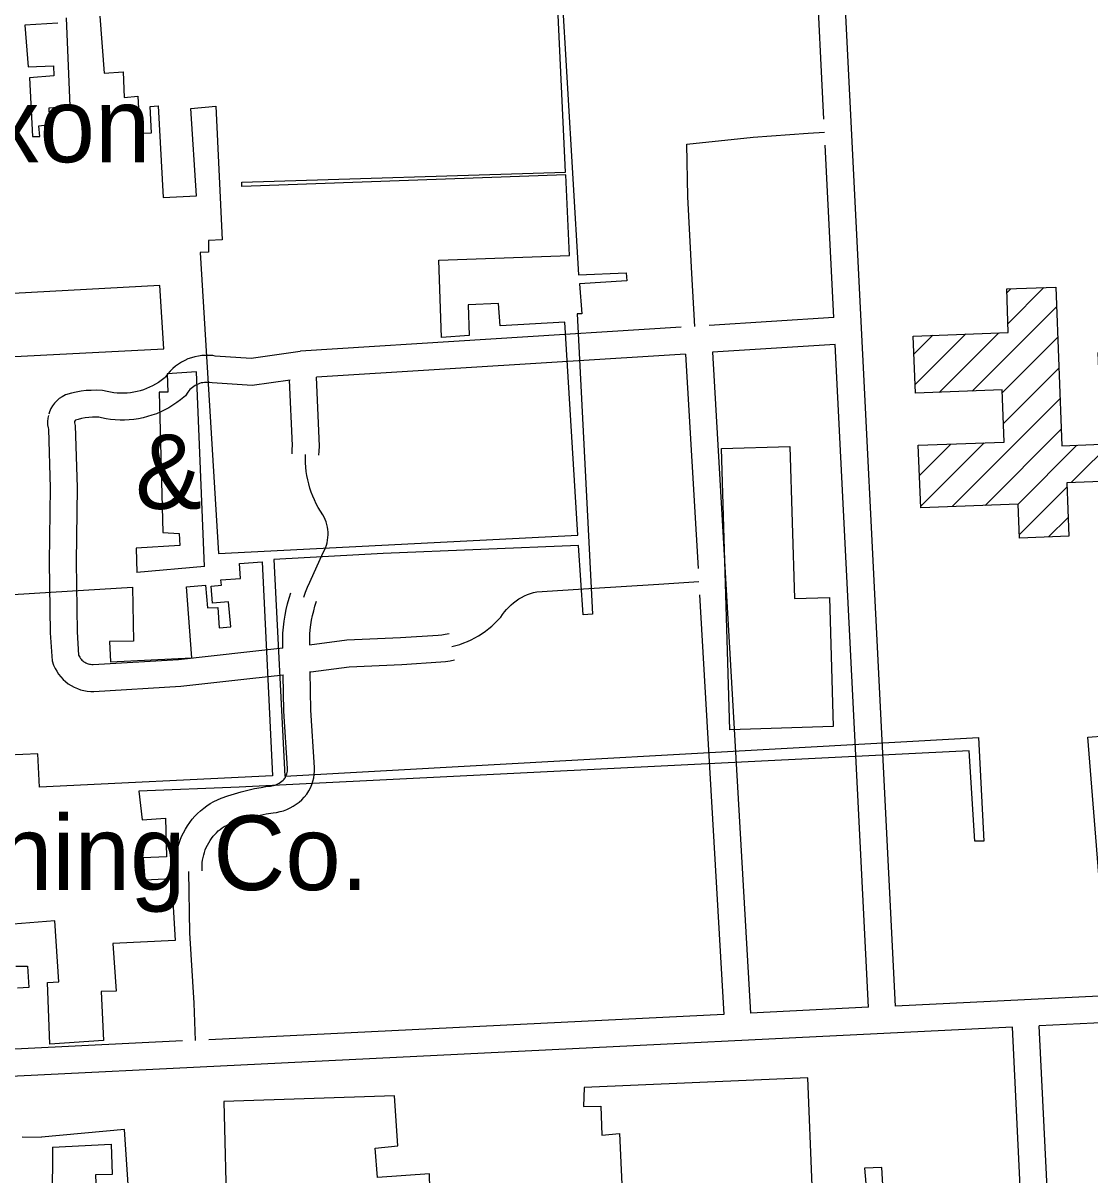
# Model space of a CAD drawing. Extents: x 3313447 to 3351316, y 703786 to 729172.
# Drawn here: x 3330659 to 3331846, y 721489 to 722771 of the extents above; entities that cross this region are included whole.
import ezdxf

# ---------------------------------------------------------------- set-up
doc = ezdxf.new("R2010")
doc.units = 0
for name, color, linetype in [('V-BLDG-IDEN', 7, 'Continuous'), ('V-BLDG-OTLN', 7, 'Continuous'), ('V-ROAD-CNTR', 7, 'Continuous'), ('V-UTIL-LINE', 7, 'Continuous')]:
    doc.layers.add(name, color=color, linetype=linetype)

msp = doc.modelspace()

# ---------------------------------------------------------------- linework, layer by layer
at = {"layer": 'V-BLDG-OTLN'}
for p, q in [((3331753.5, 722470.9), (3331758, 722475.5)), ((3331754.8, 722436.9), (3331794.8, 722476.9)), ((3331714.9, 722361.6), (3331808.6, 722455.4)), ((3331650.1, 722402.9), (3331671, 722423.8)), ((3331651.4, 722368.9), (3331707.8, 722425.2)), ((3331678.1, 722360.2), (3331744.5, 722426.6)), ((3331748.3, 722359.7), (3331809.9, 722421.3)), ((3331825.2, 722259.8), (3331968.9, 722403.5)), ((3331749.6, 722325.7), (3331811.3, 722387.3)), ((3331692.5, 722233.1), (3331812.6, 722353.2)), ((3331729.2, 722234.5), (3331813.9, 722319.2)), ((3331657.6, 722233.6), (3331728.1, 722304.1)), ((3331656.2, 722267.6), (3331691.3, 722302.7)), ((3331766, 722236), (3331831.5, 722301.5)), ((3331767.5, 722202.1), (3331820.5, 722255.1)), ((3331800, 722199.3), (3331821.8, 722221))]:
    msp.add_line(p, q, dxfattribs=at)
for points in [[(3331974.2, 722265.5), (3331820.3, 722259.6), (3331822.6, 722200.1), (3331767.6, 722198), (3331766.2, 722236), (3331657.6, 722231.8), (3331654.9, 722301.3), (3331750.4, 722305), (3331748.2, 722362.9), (3331651.8, 722359.2), (3331649.4, 722422.9), (3331755.1, 722427), (3331753.3, 722475.3), (3331807.8, 722477.4), (3331814.6, 722300.8), (3331859, 722302.6), (3331855, 722404.5), (3331968.7, 722408.9)], [(3331435.9, 722297.7), (3331512, 722300), (3331517.1, 722130.8), (3331556.1, 722131.9), (3331560.4, 721988.2), (3331445.2, 721984.7)], [(3331863.1, 721730.7), (3331843.7, 721976.4), (3331863.4, 721977.9), (3331856.9, 722060.5), (3331928, 722066.1), (3331933.8, 721992.1), (3331962.2, 721994.4), (3331982.3, 721740.1)]]:
    msp.add_lwpolyline(points, close=True, dxfattribs=at)
at = {"layer": 'V-ROAD-CNTR'}
for points in [[(3331550, 722664.2), (3331541.2, 722838.3)], [(3331629.7, 721677.3), (3331571.2, 722839.5)], [(3331406.4, 722433.7), (3331403.1, 722492.7), (3331398.4, 722578), (3331397.5, 722636.6), (3331471.1, 722644.2), (3331532.4, 722648.7), (3331550.7, 722650)], [(3331561.1, 722443.4), (3331551.4, 722635.2)], [(3331391.2, 722432.7), (3330967.7, 722406)], [(3331561.1, 722443.4), (3331422.4, 722434.7)], [(3330967.3, 722405.6), (3330912.6, 722398), (3330872.7, 722400.6), (3330869.9, 722401.1), (3330865.9, 722401.4), (3330861.9, 722401.4), (3330857.9, 722401.2), (3330853.9, 722400.6), (3330850, 722399.8), (3330846.1, 722398.7), (3330842.3, 722397.4), (3330838.7, 722395.7), (3330835.1, 722393.8), (3330831.7, 722391.7), (3330828.5, 722389.3), (3330825.4, 722386.7), (3330822.6, 722383.9), (3330819.9, 722380.9), (3330817.5, 722377.7), (3330816.9, 722376.6), (3330815.5, 722375.5), (3330812.5, 722373.3), (3330809.4, 722371.2), (3330806.3, 722369.3), (3330803, 722367.5), (3330799.7, 722365.9), (3330796.3, 722364.5), (3330792.8, 722363.2), (3330789.2, 722362.1), (3330785.7, 722361.2), (3330782, 722360.5), (3330778.4, 722359.9), (3330774.7, 722359.5), (3330771, 722359.4), (3330767.3, 722359.3), (3330763.6, 722359.5), (3330759.9, 722359.9), (3330756.2, 722360.4), (3330752.6, 722361.1), (3330747.1, 722362.5), (3330740.3, 722362.7), (3330734.7, 722362.5), (3330729.2, 722362.2), (3330723.6, 722361.5), (3330718.1, 722360.5), (3330712.7, 722359.3), (3330706.1, 722357.4), (3330702.2, 722355.4), (3330699.1, 722353.3), (3330696.3, 722350.9), (3330693.8, 722348.2), (3330691.6, 722345.2), (3330689.8, 722342.1), (3330688.3, 722338.7), (3330687.4, 722336)], [(3331562.6, 722413.4), (3331426.1, 722404.8)], [(3331599.7, 721675.9), (3331562.6, 722413.4)], [(3331396.1, 722402.9), (3330985.2, 722377)], [(3331396.1, 722402.9), (3331409.9, 722164.4)], [(3331426.1, 722404.8), (3331468.4, 721669.4)], [(3330956.2, 722373.8), (3330913.7, 722367.8), (3330869.4, 722370.8), (3330866.4, 722371.2), (3330864.5, 722371.4), (3330862.7, 722371.4), (3330860.8, 722371.3), (3330858.9, 722371), (3330857.1, 722370.7), (3330855.3, 722370.2), (3330853.6, 722369.5), (3330851.9, 722368.8), (3330850.2, 722367.9), (3330848.7, 722366.9), (3330847.2, 722365.8), (3330845.7, 722364.6), (3330844.4, 722363.3), (3330843.2, 722361.9), (3330842.1, 722360.4), (3330839.5, 722356.5), (3330834.1, 722351.9), (3330829.9, 722348.8), (3330825.6, 722345.9), (3330821.2, 722343.2), (3330816.6, 722340.8), (3330812, 722338.5), (3330807.2, 722336.5), (3330802.3, 722334.8), (3330797.4, 722333.3), (3330792.4, 722332), (3330787.3, 722330.9), (3330782.2, 722330.2), (3330777, 722329.6), (3330771.8, 722329.4), (3330766.7, 722329.3), (3330761.5, 722329.6), (3330756.3, 722330.1), (3330751.2, 722330.8), (3330746.1, 722331.8), (3330743, 722332.6), (3330740.2, 722332.7), (3330736.1, 722332.6), (3330732, 722332.3), (3330728, 722331.8), (3330724, 722331.1), (3330720.1, 722330.2), (3330717.3, 722329.4), (3330717.7, 722329.6), (3330717.4, 722329.4), (3330717.1, 722329.2), (3330716.9, 722328.9), (3330716.7, 722328.6), (3330716.5, 722328.3), (3330716.3, 722328), (3330716, 722326.9)], [(3330958.1, 722292), (3330958.4, 722297.1), (3330958.8, 722301), (3330955.4, 722373.7)], [(3330988, 722290.2), (3330988.3, 722294.7), (3330988.8, 722300.2), (3330985.3, 722377)], [(3330687, 722334.4), (3330686.4, 722331.6), (3330686.1, 722327.9), (3330686.2, 722324.2), (3330686.7, 722320.6), (3330687, 722319.4), (3330689.1, 722254), (3330688, 722171.5), (3330689, 722092.5), (3330691.1, 722061.5), (3330692.8, 722056.6), (3330694.4, 722053.1), (3330696.3, 722049.8), (3330698.4, 722046.6), (3330700.7, 722043.6), (3330703.3, 722040.8), (3330706.2, 722038.3), (3330709.2, 722035.9), (3330712.4, 722033.9), (3330715.8, 722032.1), (3330719.3, 722030.6), (3330722.9, 722029.3), (3330726.6, 722028.4), (3330730.3, 722027.8), (3330734.1, 722027.5), (3330737.7, 722027.5), (3330834.4, 722033.2), (3330911, 722041.7), (3330948.6, 722045.7)], [(3330716.4, 722328.5), (3330716.2, 722327.3), (3330716.1, 722327), (3330716.1, 722326.6), (3330716.2, 722326.2), (3330716.9, 722323.5), (3330719.1, 722254.3), (3330718, 722171.5), (3330719, 722093.7), (3330720.7, 722067.7), (3330720.7, 722067.8), (3330721.3, 722066.5), (3330721.9, 722065.4), (3330722.7, 722064.2), (3330723.5, 722063.2), (3330724.4, 722062.2), (3330725.4, 722061.3), (3330726.5, 722060.5), (3330727.6, 722059.8), (3330728.8, 722059.1), (3330730, 722058.6), (3330731.3, 722058.2), (3330732.6, 722057.8), (3330733.9, 722057.6), (3330735.3, 722057.5), (3330736.8, 722057.5), (3330831.8, 722063.1), (3330907.7, 722071.5), (3330948, 722075.8)], [(3330971.1, 722132.4), (3330973.2, 722138), (3330975.5, 722143.5), (3330978, 722148.9), (3330992.8, 722182), (3330994.2, 722184.6), (3330995.4, 722187.3), (3330996.4, 722190.1), (3330997.1, 722192.9), (3330997.7, 722195.8), (3330998.1, 722198.7), (3330998.3, 722201.6), (3330998.2, 722204.6), (3330998, 722207.5), (3330997.5, 722210.4), (3330996.9, 722213.3), (3330996, 722216.1), (3330995, 722218.8), (3330993.8, 722221.5), (3330992.3, 722224.1), (3330989.7, 722228), (3330987.3, 722232.1), (3330985.1, 722236.3), (3330983, 722240.5), (3330981.2, 722244.9), (3330979.5, 722249.3), (3330978, 722253.8), (3330976.7, 722258.3), (3330975.6, 722262.9), (3330974.6, 722267.6), (3330973.9, 722272.3), (3330973.4, 722277), (3330973.1, 722281.7), (3330973, 722286.4), (3330973, 722291.1)], [(3331135.9, 722077.3), (3331140.3, 722078.5), (3331144.7, 722079.8), (3331149.1, 722081.4), (3331153.3, 722083.1), (3331157.5, 722085), (3331161.6, 722087.1), (3331165.6, 722089.4), (3331169.5, 722091.9), (3331173.3, 722094.5), (3331177, 722097.3), (3331180.5, 722100.2), (3331183.9, 722103.3), (3331187.1, 722106.6), (3331190.3, 722110), (3331192.2, 722113), (3331194.4, 722115.9), (3331196.7, 722118.7), (3331199.2, 722121.3), (3331201.8, 722123.8), (3331204.6, 722126.1), (3331207.5, 722128.3), (3331210.5, 722130.3), (3331213.6, 722132.1), (3331216.8, 722133.7), (3331220.1, 722135.2), (3331223.5, 722136.5), (3331226.9, 722137.5), (3331230.4, 722138.4), (3331288.3, 722142), (3331366.4, 722146.6), (3331410.7, 722149.6)], [(3330948, 722075.7), (3330947.9, 722092.2), (3330948.5, 722099.1), (3330949.3, 722105.6), (3330950.3, 722112.1), (3330951.6, 722118.5), (3330953.2, 722124.8), (3330954.9, 722131.1), (3330956.9, 722137.1)], [(3330978, 722079.1), (3330977.9, 722091.1), (3330978.3, 722096.1), (3330979, 722101.4), (3330979.8, 722106.7), (3330980.9, 722112), (3330982.2, 722117.2), (3330983.6, 722122.4), (3330985.4, 722127.8)], [(3331411.6, 722134.9), (3331438.5, 721667.9)], [(3330977.7, 722079.3), (3331019.1, 722084.8), (3331078.8, 722087.5), (3331120.9, 722090.1), (3331124.7, 722090.5), (3331128.6, 722091.1), (3331132.8, 722092)], [(3330979, 722049.3), (3331021.7, 722054.8), (3331080.4, 722057.5), (3331123.6, 722060.2), (3331128.9, 722060.8), (3331134.1, 722061.6), (3331138.9, 722062.7)], [(3330858.2, 721827.7), (3330858.1, 721831), (3330858.1, 721833.9), (3330858.3, 721836.9), (3330858.6, 721839.8), (3330859.1, 721842.6), (3330859.8, 721845.5), (3330860.6, 721848.3), (3330861.6, 721851.1), (3330862.7, 721853.8), (3330864, 721856.4), (3330865.4, 721859), (3330866.9, 721861.5), (3330868.6, 721863.9), (3330870.3, 721866.2), (3330872.1, 721868.3), (3330874, 721870.2), (3330876.1, 721872.1), (3330878.2, 721873.8), (3330880.4, 721875.5), (3330882.7, 721876.9), (3330885.1, 721878.3), (3330887.5, 721879.5), (3330890.1, 721880.6), (3330896.3, 721882.8), (3330902.7, 721884.8), (3330909.3, 721886.7), (3330915.9, 721888.4), (3330922.5, 721889.8), (3330929.3, 721891.1), (3330934.5, 721892.1), (3330937, 721892.2), (3330941, 721892.7), (3330944.9, 721893.6), (3330948.7, 721894.7), (3330952.4, 721896.1), (3330956, 721897.7), (3330959.5, 721899.7), (3330962.8, 721901.8), (3330966, 721904.3), (3330968.9, 721906.9), (3330971.7, 721909.8), (3330974.5, 721913.2), (3330976.8, 721916.8), (3330978.5, 721920.2), (3330980, 721923.8), (3330981.3, 721927.5), (3330982.2, 721931.2), (3330982.8, 721935), (3330983.2, 721938.9), (3330983.2, 721942.7), (3330979, 722006.7), (3330978.3, 722049.7)], [(3330828.2, 721826.4), (3330828, 721830.6), (3330828.1, 721835.1), (3330828.4, 721839.7), (3330829, 721844.2), (3330829.7, 721848.7), (3330830.8, 721853.1), (3330832, 721857.5), (3330833.6, 721861.8), (3330835.3, 721866), (3330837.2, 721870.1), (3330839.4, 721874.1), (3330841.8, 721877.9), (3330844.4, 721881.6), (3330847, 721885.1), (3330849.9, 721888.5), (3330853.1, 721891.7), (3330856.3, 721894.7), (3330859.8, 721897.6), (3330863.4, 721900.2), (3330867.2, 721902.6), (3330871.1, 721904.8), (3330875.1, 721906.8), (3330879.2, 721908.5), (3330886.7, 721911.2), (3330894, 721913.6), (3330901.5, 721915.7), (3330909, 721917.6), (3330916.5, 721919.2), (3330923.9, 721920.6), (3330930.9, 721921.9), (3330934.1, 721922.1), (3330935.8, 721922.3), (3330937.5, 721922.7), (3330939.2, 721923.2), (3330940.8, 721923.8), (3330942.4, 721924.5), (3330943.9, 721925.4), (3330945.4, 721926.3), (3330946.8, 721927.4), (3330948.1, 721928.5), (3330949.3, 721929.8), (3330950.1, 721930.8), (3330950.7, 721931.7), (3330951.4, 721933), (3330952, 721934.4), (3330952.4, 721935.8), (3330952.8, 721937.3), (3330953, 721938.7), (3330953.2, 721940.2), (3330953.2, 721941.8), (3330949, 722005.5), (3330948.3, 722046)], [(3330850.8, 721639.1), (3330849.4, 721680.5), (3330844.5, 721758.6), (3330843.2, 721827)], [(3332075.4, 721699.2), (3331629.7, 721677.3)], [(3331599.7, 721675.9), (3331468.4, 721669.4)], [(3332321.7, 721681.3), (3331789.6, 721655.2)], [(3331438.5, 721667.9), (3330865.7, 721639.8)], [(3331759.7, 721653.7), (3330434, 721588.6), (3330388, 721587.2)], [(3331781.9, 721234), (3331774.2, 721352.8), (3331759.7, 721653.7)], [(3331866.6, 720202.8), (3331863, 720265.4), (3331831.4, 720935.3), (3331804.2, 721354.5), (3331789.6, 721655.2)], [(3330836.1, 721638.4), (3330432.8, 721618.6), (3330389.2, 721617.3)]]:
    msp.add_lwpolyline(points, dxfattribs=at)
at = {"layer": 'V-UTIL-LINE'}
for p, q in [((3330860.9, 722166.6), (3330785.5, 722159.7)), ((3330691.5, 721520.3), (3330690.9, 721409.1))]:
    msp.add_line(p, q, dxfattribs=at)
for points in [[(3331258, 722812), (3331276.7, 722491), (3331330, 722493.2), (3331330.8, 722484.3), (3331277.9, 722481), (3331280.4, 722447.5), (3331275.5, 722447.5), (3331292.6, 722113.3), (3331282.1, 722112.8), (3331276.8, 722189.8), (3331059.4, 722181), (3330937.9, 722174.3), (3330950.2, 721933), (3331722.1, 721976), (3331727.8, 721860.6), (3331717.8, 721860.8), (3331711.6, 721961.4), (3330899.4, 721920.8), (3330787.8, 721916.3), (3330791.3, 721884.5), (3330817.2, 721886.5), (3330818.6, 721843.2), (3330792.4, 721842.1), (3330794.2, 721817.8), (3330823.9, 721819.3), (3330828.2, 721750.1), (3330758.9, 721746.9), (3330762.3, 721693.8), (3330745.9, 721693.3), (3330748.3, 721639), (3330688.6, 721634.9), (3330685.9, 721703.5), (3330698.5, 721704.3), (3330694.2, 721772.1), (3330647.9, 721768.4)], [(3330744.4, 722779), (3330748.9, 722715.6), (3330770.4, 722716.9), (3330771.3, 722688.4), (3330786.5, 722689.8), (3330788.6, 722648.7), (3330801.7, 722649.2), (3330800.1, 722678.4), (3330809, 722679.2), (3330814.7, 722577.2), (3330851.7, 722578.8), (3330845.5, 722676.3), (3330873.2, 722678.8), (3330880.2, 722530), (3330865, 722529.2), (3330865.3, 722516.1), (3330855.9, 722515.8), (3330876.4, 722181), (3331276.3, 722201.3), (3331261.5, 722438.5), (3331189.7, 722434.2), (3331187.7, 722459.2), (3331154.2, 722457.6), (3331155.3, 722423.5), (3331124.6, 722421.4), (3331121.4, 722507.3), (3331267, 722512.5), (3331262.8, 722602.4), (3330902.4, 722589.3), (3330902.4, 722594), (3331262.5, 722605.4), (3331253.1, 722804.3)], [(3330697.6, 722771.3), (3330660.9, 722769), (3330664.4, 722722.7), (3330692.7, 722723.8), (3330693.2, 722712.5), (3330665.9, 722710.3), (3330669.5, 722645), (3330677.4, 722645.1), (3330676.4, 722657), (3330688.6, 722658.2), (3330687.8, 722676.9), (3330711.2, 722678.9), (3330707.2, 722777)], [(3330418, 722388.1), (3330815.4, 722408.8), (3330811.2, 722479), (3330409.4, 722457.3)], [(3330860.9, 722166.6), (3330851.8, 722383), (3330819.3, 722380.7), (3330820.1, 722360.3), (3330810.1, 722360.3), (3330814.3, 722204.1), (3330832.7, 722203.2), (3330833.1, 722190), (3330784.6, 722186.7), (3330785.5, 722159.7)], [(3330556.1, 722129.8), (3330780.7, 722143.4), (3330781.7, 722083.5), (3330755, 722083), (3330756.2, 722060.5), (3330846.5, 722064.8), (3330840.6, 722143.7), (3330862, 722145.5), (3330863.9, 722120.3), (3330875.7, 722120.7), (3330877.2, 722098.2), (3330890, 722099.3), (3330887.4, 722127), (3330869.8, 722125.8), (3330868.3, 722144.5), (3330879.7, 722145.6), (3330879, 722151.5), (3330900.8, 722153), (3330899.7, 722169.6), (3330924.9, 722171.8), (3330936.5, 721933.3), (3330677.3, 721920.9), (3330675.3, 721958), (3330641.8, 721956.4)], [(3330650.7, 721721.6), (3330663.8, 721721.6), (3330665.1, 721697.8), (3330652.7, 721697.2)], [(3331536.9, 721477.1), (3331532, 721597.5), (3331283.3, 721586.7), (3331282.4, 721565.5), (3331301.6, 721565.9), (3331302.8, 721533.5), (3331322.3, 721535.3), (3331326.3, 721454.5)], [(3330984.6, 721212.6), (3330978.8, 721211.6), (3330971.2, 721353.8), (3331117.4, 721361.5), (3331115.6, 721385.3), (3331094.8, 721384.6), (3331091.9, 721423.3), (3331112.7, 721424.4), (3331111.1, 721490.5), (3331053.2, 721486.3), (3331050.7, 721519), (3331075.9, 721521.8), (3331072, 721577.3), (3330882.1, 721571.1), (3330885.7, 721436.8), (3330779.2, 721428.7)], [(3330779.2, 721428.7), (3330771.7, 721539.9), (3330679.4, 721531.2)], [(3330657.7, 721531.8), (3330679.4, 721531.2)], [(3330691.5, 721520.3), (3330756.8, 721523.4), (3330757.9, 721489.7), (3330739.6, 721489.4), (3330741, 721452.2), (3330760.9, 721453), (3330761.6, 721352.8), (3330745.7, 721352), (3330746.6, 721311.1), (3330765.3, 721312.8), (3330766.5, 721269.7), (3330716.4, 721265.5), (3330713.5, 721382.3), (3330721.9, 721382.8), (3330720.8, 721409.7), (3330690.9, 721409.1)], [(3331616, 721471.6), (3331614.3, 721497.4), (3331595.1, 721496.9), (3331596.5, 721479.7)]]:
    msp.add_lwpolyline(points, dxfattribs=at)

# ---------------------------------------------------------------- texts
at = {"layer": 'V-BLDG-IDEN'}
for s, p in [('Exxon', (3330492.1, 722616.4)), ('&', (3330783.7, 722230.6)), ('Refining Co.', (3330432.4, 721806.3))]:
    msp.add_text(s, height=83, dxfattribs=at).set_placement(p)

doc.saveas('drawing.dxf')
